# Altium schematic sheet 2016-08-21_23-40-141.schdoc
size 424 x 220 mm; SheetNumber: 1; SheetTotal: 1
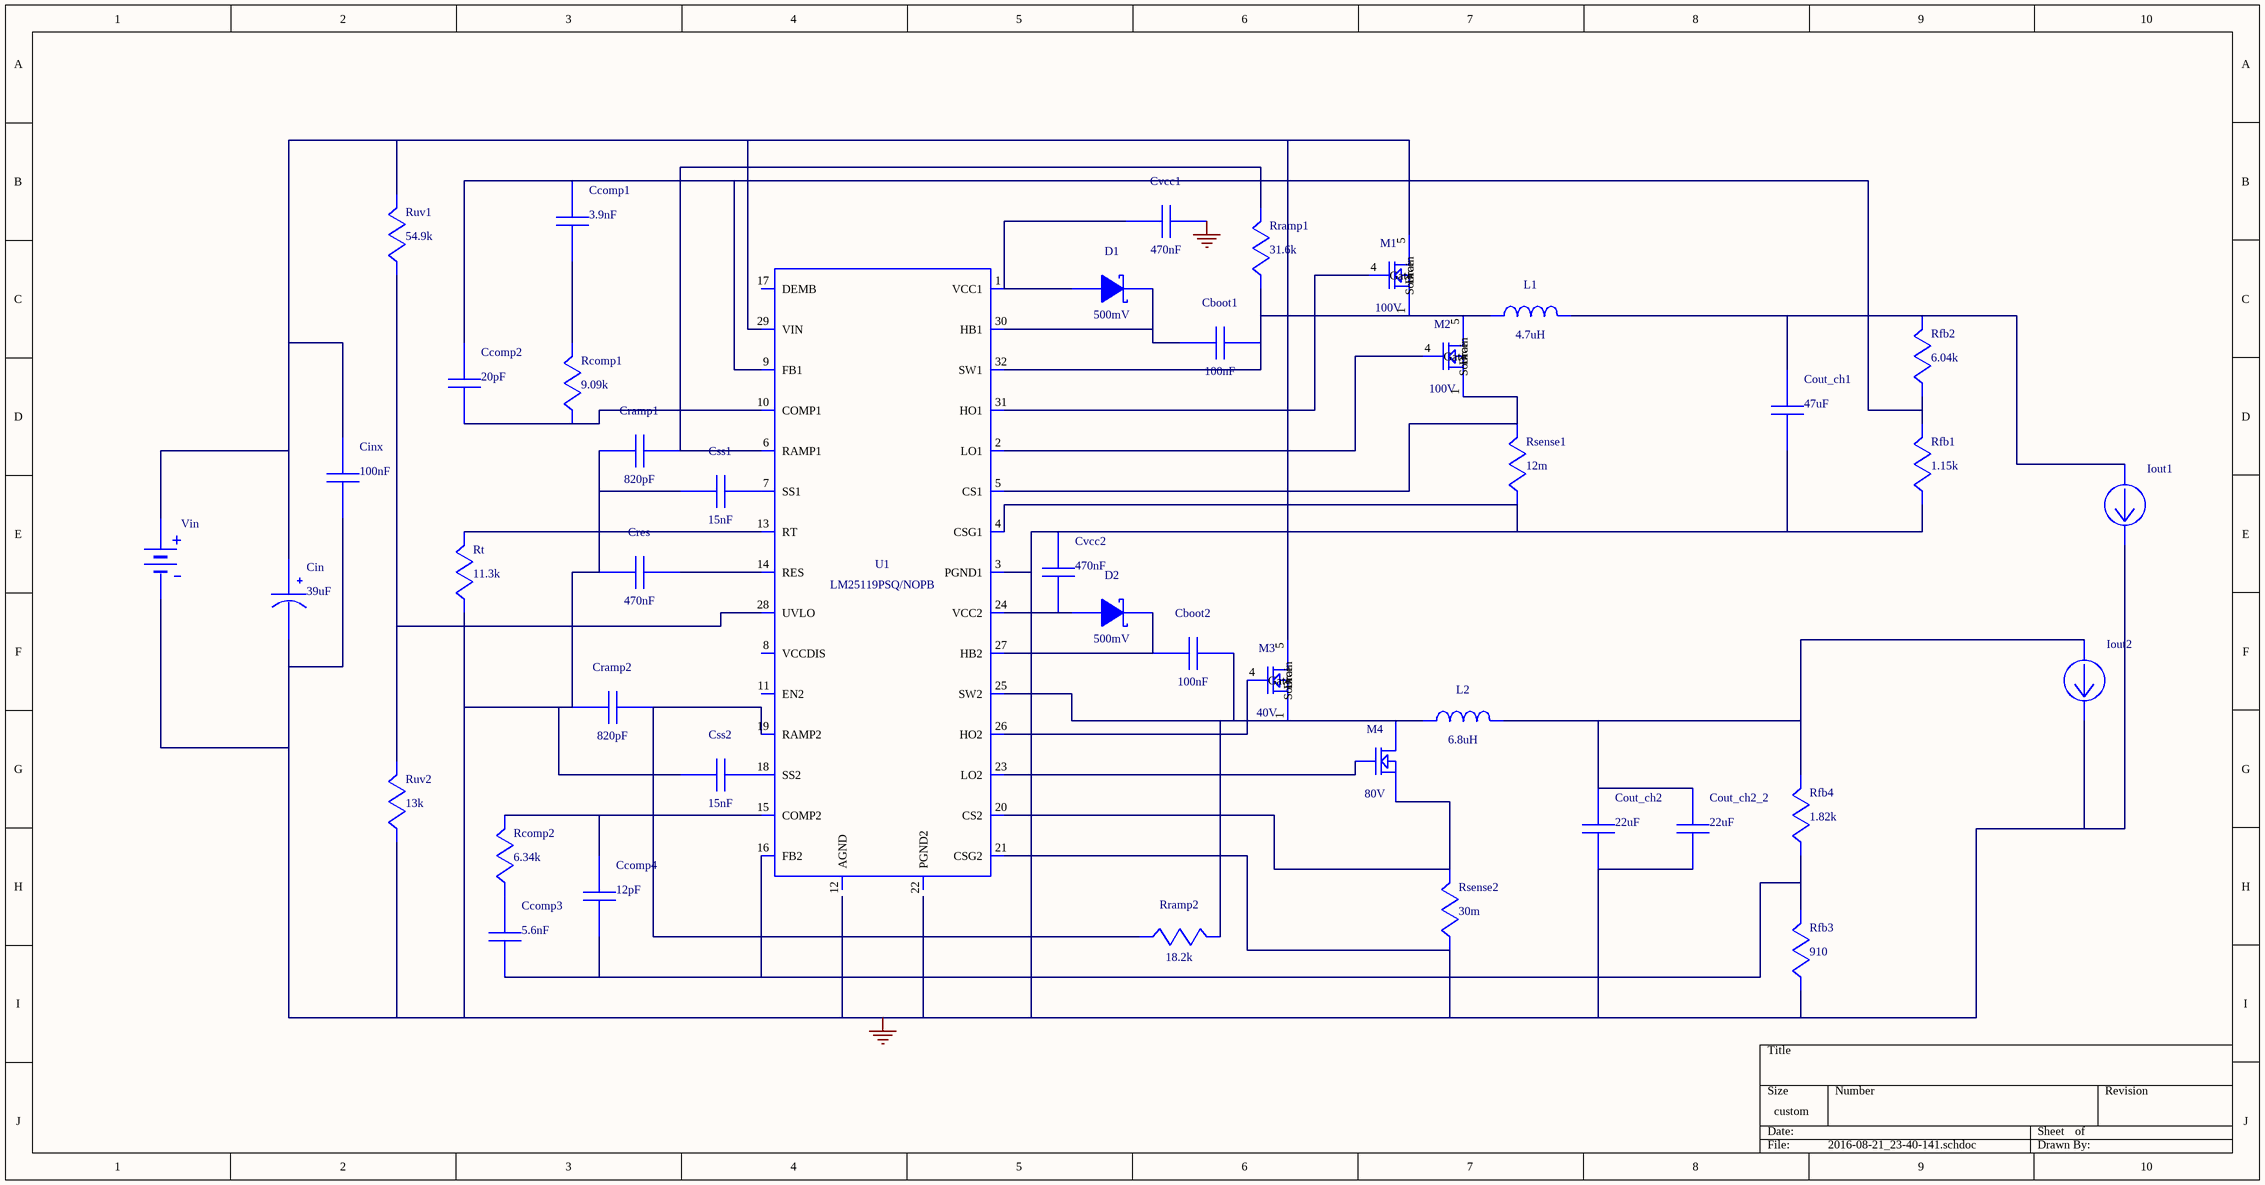
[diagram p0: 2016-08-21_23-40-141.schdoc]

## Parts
Cboot1  value 100nF  (hidden comment: GRM155R61A104KA01D)
Cboot2  value 100nF  (hidden comment: GRM155R61A104KA01D)
Ccomp1  value 3.9nF  (hidden comment: CC0805KRX7R9BB392)
Ccomp2  value 20pF  (hidden comment: CL21C200JBANNNC)
Ccomp3  value 5.6nF  (hidden comment: CC0805KRX7R9BB562)
Ccomp4  value 12pF  (hidden comment: CC0805JRNPO9BN120)
Cin  value 39uF  (hidden comment: GENERIC_CAP_POLARIZED)
Cinx  value 100nF  (hidden comment: C0805C104K5RACTU)
Cout_ch1  value 47uF  (hidden comment: GRM31CR61A476KE15L)
Cout_ch2  value 22uF  (hidden comment: GRM21BC80G226ME39L)
Cout_ch2_2  value 22uF  (hidden comment: GRM21BC80G226ME39L)
Cramp1  value 820pF  (hidden comment: CC0805KRX7R9BB821)
Cramp2  value 820pF  (hidden comment: CC0805KRX7R9BB821)
Cres  value 470nF  (hidden comment: GRM155C80J474KE19D)
Css1  value 15nF  (hidden comment: CC0805KRX7R9BB153)
Css2  value 15nF  (hidden comment: CC0805KRX7R9BB153)
Cvcc1  value 470nF  (hidden comment: GRM155R61A474KE15D)
Cvcc2  value 470nF  (hidden comment: GRM155R61A474KE15D)
D1  value 500mV  (hidden comment: SS14-E3/61T)
D2  value 500mV  (hidden comment: SS14-E3/61T)
Iout1  WB_CURRENT_LOAD  (value not drawn)
Iout2  WB_CURRENT_LOAD  (value not drawn)
L1  value 4.7uH  (hidden comment: SRR1280-4R7Y)
L2  value 6.8uH  (hidden comment: SDR0805-6R8ML)
M1  value 100V  (hidden comment: CSD19537Q3)
M2  value 100V  (hidden comment: CSD19537Q3)
M3  value 40V  (hidden comment: CSD18504Q5A)
M4  value 80V  (hidden comment: BSC340N08NS3 G)
Rcomp1  value 9.09k  (hidden comment: CRCW04029K09FKED)
Rcomp2  value 6.34k  (hidden comment: CRCW04026K34FKED)
Rfb1  value 1.15k  (hidden comment: CRCW04021K15FKED)
Rfb2  value 6.04k  (hidden comment: CRCW04026K04FKED)
Rfb3  value 910  (hidden comment: RC0603FR-07910RL)
Rfb4  value 1.82k  (hidden comment: CRCW04021K82FKED)
Rramp1  value 31.6k  (hidden comment: CRCW040231K6FKED)
Rramp2  value 18.2k  (hidden comment: CRCW040218K2FKED)
Rsense1  value 12m  (hidden comment: CSR1206FK12L0)
Rsense2  value 30m  (hidden comment: CSR1206FK30L0)
Rt  value 11.3k  (hidden comment: CRCW040211K3FKED)
Ruv1  value 54.9k  (hidden comment: CRCW040254K9FKED)
Ruv2  value 13k  (hidden comment: CRCW040213K0FKED)
U1  LM25119PSQ/NOPB
Vin  WB_BATTERY  (value not drawn)

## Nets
0: Cin.2(-) Cinx.2 Cout_ch1.2 Cout_ch2.2 Cout_ch2_2.2 Cramp1.2 Cramp2.2 Cres.2 Css1.2 Css2.2 Cvcc1.2 Cvcc2.2 Iout1.2(-) Iout2.2(-) Rfb1.2 Rfb3.2 Rsense1.2 Rsense2.2 Rt.2 Ruv2.2 U1.3(PGND1) U1.4(CSG1) U1.21(CSG2) U1.33(EP) Vin.2(-)
NetCboot1_1: Cboot1.1 L1.1 M1.1(Source) M1.2(Source) M1.3(Source) M2.5(Drain) M2.6(Drain) M2.7(Drain) M2.8(Drain) M2.9(Drain) Rramp1.2 U1.32(SW1)
NetCboot1_2: Cboot1.2 D1.1(K) U1.30(HB1)
NetCboot2_1: Cboot2.1 L2.1 M3.1(Source) M3.2(Source) M3.3(Source) M4.5(Drain) M4.6(Drain) M4.7(Drain) M4.8(Drain) M4.9(Drain) Rramp2.1 U1.25(SW2)
NetCboot2_2: Cboot2.2 D2.1(K) U1.27(HB2)
NetCcomp1_1: Ccomp1.1 Rcomp1.1
NetCcomp1_2: Ccomp1.2 Ccomp2.2 Rfb1.1 Rfb2.2 U1.9(FB1)
NetCcomp2_1: Ccomp2.1 Rcomp1.2 U1.10(COMP1)
NetCcomp3_1: Ccomp3.1 Rcomp2.2
NetCcomp3_2: Ccomp3.2 Ccomp4.2 Rfb3.1 Rfb4.2 U1.16(FB2)
NetCcomp4_1: Ccomp4.1 Rcomp2.1 U1.15(COMP2)
NetCin_1: Cin.1(+) Cinx.1 M1.5(Drain) M1.6(Drain) M1.7(Drain) M1.8(Drain) M1.9(Drain) M3.5(Drain) M3.6(Drain) M3.7(Drain) M3.8(Drain) M3.9(Drain) Ruv1.1 U1.29(VIN) Vin.1(+)
NetCout_ch1_1: Cout_ch1.1 Iout1.1(+) L1.2 Rfb2.1
NetCout_ch2_1: Cout_ch2.1 Cout_ch2_2.1 Iout2.1(+) L2.2 Rfb4.1
NetCramp1_1: Cramp1.1 Rramp1.1 U1.6(RAMP1)
NetCramp2_1: Cramp2.1 Rramp2.2 U1.19(RAMP2)
NetCres_1: Cres.1 U1.14(RES)
NetCss1_1: Css1.1 U1.7(SS1)
NetCss2_1: Css2.1 U1.18(SS2)
NetCvcc1_1: Cvcc1.1 D1.2(A) U1.1(VCC1)
NetCvcc2_1: Cvcc2.1 D2.2(A) U1.24(VCC2)
NetM1_4: M1.4(Gate) U1.31(HO1)
NetM2_1: M2.1(Source) M2.2(Source) M2.3(Source) Rsense1.1 U1.5(CS1)
NetM2_4: M2.4(Gate) U1.2(LO1)
NetM3_4: M3.4(Gate) U1.26(HO2)
NetM4_1: M4.1(Source) M4.2(Source) M4.3(Source) Rsense2.1 U1.20(CS2)
NetM4_4: M4.4(Gate) U1.23(LO2)
NetRt_1: Rt.1 U1.13(RT)
NetRuv1_2: Ruv1.2 Ruv2.1 U1.28(UVLO)

Not connected (* = marked no-connect by the designer): U1 8(VCCDIS) 11(EN2) 12(AGND) 17(DEMB) 22(PGND2)

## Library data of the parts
Cboot1 Cboot2 = GRM155R61A104KA01D: GRM155R61A104KA0; Manufacturer Name: MuRata
Ccomp1 = CC0805KRX7R9BB392: CC0805KRX7R9BB39; Manufacturer Name: Yageo America
Ccomp2 = CL21C200JBANNNC: Manufacturer Name: Samsung Electro-Mechanics
Ccomp3 = CC0805KRX7R9BB562: CC0805KRX7R9BB56; Manufacturer Name: Yageo America
Ccomp4 = CC0805JRNPO9BN120: CC0805JRNPO9BN12; Manufacturer Name: Yageo America
Cin = GENERIC_CAP_POLARIZED: 50SVPF39M; Manufacturer Name: Panasonic
Cinx = C0805C104K5RACTU: Manufacturer Name: Kemet
Cout_ch1 = GRM31CR61A476KE15L: GRM31CR61A476KE1; Manufacturer Name: MuRata
Cout_ch2 Cout_ch2_2 = GRM21BC80G226ME39L: GRM21BC80G226ME3; Manufacturer Name: MuRata
Cramp1 Cramp2 = CC0805KRX7R9BB821: CC0805KRX7R9BB82; Manufacturer Name: Yageo America
Cres = GRM155C80J474KE19D: GRM155C80J474KE1; Manufacturer Name: MuRata
Css1 Css2 = CC0805KRX7R9BB153: CC0805KRX7R9BB15; Manufacturer Name: Yageo America
Cvcc1 Cvcc2 = GRM155R61A474KE15D: GRM155R61A474KE1; Manufacturer Name: MuRata
D1 D2 = SS14-E3/61T: Manufacturer Name: Vishay-Semiconductor
L1 = SRR1280-4R7Y: Manufacturer Name: Bourns
L2 = SDR0805-6R8ML: Manufacturer Name: Bourns
M1 M2 = CSD19537Q3: Manufacturer Name: Texas Instruments
M3 = CSD18504Q5A: Manufacturer Name: Texas Instruments
M4 = BSC340N08NS3 G: Manufacturer Name: Infineon Technologies
Rcomp1 = CRCW04029K09FKED: Manufacturer Name: Vishay-Dale
Rcomp2 = CRCW04026K34FKED: Manufacturer Name: Vishay-Dale
Rfb1 = CRCW04021K15FKED: Manufacturer Name: Vishay-Dale
Rfb2 = CRCW04026K04FKED: Manufacturer Name: Vishay-Dale
Rfb3 = RC0603FR-07910RL: Manufacturer Name: Yageo America
Rfb4 = CRCW04021K82FKED: Manufacturer Name: Vishay-Dale
Rramp1 = CRCW040231K6FKED: Manufacturer Name: Vishay-Dale
Rramp2 = CRCW040218K2FKED: Manufacturer Name: Vishay-Dale
Rsense1 = CSR1206FK12L0: Manufacturer Name: Stackpole Electronics Inc
Rsense2 = CSR1206FK30L0: Manufacturer Name: Stackpole Electronics Inc
Rt = CRCW040211K3FKED: Manufacturer Name: Vishay-Dale
Ruv1 = CRCW040254K9FKED: Manufacturer Name: Vishay-Dale
Ruv2 = CRCW040213K0FKED: Manufacturer Name: Vishay-Dale
U1 = LM25119PSQ/NOPB: Manufacturer Name: Texas Instruments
